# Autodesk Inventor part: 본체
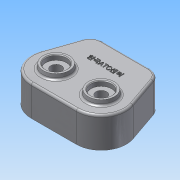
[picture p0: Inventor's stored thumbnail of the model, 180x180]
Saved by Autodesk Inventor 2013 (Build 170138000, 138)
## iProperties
Created: 2014-12
Part Number: 본체
Material: 알루미늄 6061
Document SubType Name: Modeling
Designer: Administrator
Density: 2.71 g/cm^3
Mass: 613.436 g
Surface Area: 665.181 cm^2
Volume: 226.36 cm^3
Author: Administrator
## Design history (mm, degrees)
sketch "스케치1"
  geometry: L1 (47, 36)-(-47, 36); L2 (32.527, -68.527)-(-32.527, -68.527); L3 (47, 36)-(66.565, -20.803); L4 (-47, 36)-(-66.565, -20.803); A1 r 36 centre (32.527, -32.527) between (32.527, -68.527) and (66.565, -20.803); A2 r 36 centre (-32.527, -32.527) between (-66.565, -20.803) and (-32.527, -68.527); 3 further points
  constraints: 8 end point, 4 point on circle, 3 tangent, 2 centre point, 2 midpoint, 2 vertical alignment, 1 horizontal, 1 horizontal alignment
  dimensions: "d18" = 94 distance of L1.start L1.end; "d19" = 72 diameter of A1; "d20" = 72 diameter of A2; "d21" = 36 distance from line of point (0, 0) L1; "d22" = 46 distance of A1.centre point (0, 0); "d23" = 90 deg dimension on point (0, 0) A2.centre A1.centre; "d24" = 46 distance of A2.centre point (0, 0)
extrude "돌출1" new body sketch "스케치1" distance "d25" = 44; taper "d26" = 0 deg
sketch "스케치2"
  geometry: L1 (-43.434, 31)-(43.434, 31); L2 (43.434, 31)-(61.837, -22.432); L3 (-43.434, 31)-(-61.837, -22.432); L4 (-66.565, -20.803)-(-47, 36) reference; L5 (47, 36)-(66.565, -20.803) reference; L6 (-32.527, -63.527)-(32.527, -63.527); L7 (-47, 36)-(47, 36) reference; A1 r 36 centre (-32.527, -32.527) between (-66.565, -20.803) and (-32.527, -68.527) reference; A2 r 36 centre (32.527, -32.527) between (32.527, -68.527) and (66.565, -20.803) reference; A3 r 31 centre (-32.527, -32.527) between (-61.837, -22.432) and (-32.527, -63.527); A4 r 31 centre (32.527, -32.527) between (32.527, -63.527) and (61.837, -22.432); 1 further point
  constraints: 8 end point, 4 point on circle, 3 parallel, 3 tangent, 2 centre point, 2 coincident, 1 horizontal
  dimensions: "d29" = 5 distance between parallel lines of L4 L3; "d30" = 5 distance between parallel lines of L7 L1; "d31" = 5 distance between parallel lines of L2 L5
extrude "돌출2" cut sketch "스케치2" distance "d32" = 34; taper "d33" = 0 deg
sketch "스케치3"
  geometry: L1 (47, 36)-(-47, 36) reference; L2 (-47, 36)-(-66.565, -20.803) reference; L3 (-32.527, -68.527)-(32.527, -68.527) reference; L4 (66.565, -20.803)-(47, 36) reference; C1 r 20 at (-32.527, -32.527); C2 r 20 at (32.527, -32.527); A1 r 36 centre (-32.527, -32.527) between (-66.565, -20.803) and (-32.527, -68.527) reference; A2 r 36 centre (32.527, -32.527) between (32.527, -68.527) and (66.565, -20.803) reference; A3 r 36 centre (-32.527, -32.527) between (-66.565, -20.803) and (-32.527, -68.527) reference; A4 r 36 centre (32.527, -32.527) between (32.527, -68.527) and (66.565, -20.803) reference; 1 further point
  constraints: 2 centre point, 2 coincident
  dimensions: "d34" = 40 diameter of C1; "d35" = 40 diameter of C2
extrude "돌출3" join sketch "스케치3" distance "d36" = 7; taper "d37" = -10 deg
sketch "스케치4"
  geometry: A1 r 36 centre (-32.527, -32.527) between (-66.565, -20.803) and (-32.527, -68.527) reference; A2 r 36 centre (32.527, -32.527) between (32.527, -68.527) and (66.565, -20.803) reference; A3 r 24 centre (-32.527, -32.527) between (-21.111, -11.416) and (-11.416, -21.111); A4 r 24 centre (32.527, -32.527) between (11.416, -21.111) and (21.111, -11.416); A5 r 24 centre (0, 0) between (-11.416, -21.111) and (11.416, -21.111); A6 r 24 centre (0, 0) between (21.111, -11.416) and (-21.111, -11.416); 1 further point
  constraints: 8 point on circle, 4 centre point, 3 coincident
  dimensions: "d39" = 48 diameter of A3; "d40" = 48 diameter of A4; "d41" = 24 radius of A6; "d42" = 24 radius of A5
extrude "돌출4" join sketch "스케치4" distance "d43" = 11; taper "d44" = 0 deg
hole "구멍1" diameter "d47" = 20; stored, may be unused: countersink angle "d51" = 90 deg, drill point angle "d53" = 0 deg; dims "d45" = 10, "d46" = 10, "d48" = 6, "d49" = 40, "d50" = 12, "d52" = 15
hole "구멍2" diameter "d56" = 15.5; stored, may be unused: countersink angle "d60" = 90 deg, drill point angle "d62" = 0 deg; dims "d54" = 10, "d55" = 10, "d57" = 6, "d58" = 35, "d59" = 11, "d61" = 21
hole "구멍3" diameter "d65" = 15.5; stored, may be unused: countersink angle "d69" = 90 deg, drill point angle "d71" = 0 deg; dims "d63" = 10, "d64" = 10, "d66" = 6, "d67" = 35, "d68" = 11, "d70" = 21
sketch "스케치5"
  geometry: C1 r 18.766 at (0, 0) reference; C2 r 18.766 at (65.054, 0) reference; C3 r 15 at (0, 0); C4 r 15 at (65.054, 0); 1 further point
  constraints: 2 centre point, 2 coincident
  dimensions: "d72" = 30 diameter of C3; "d73" = 30 diameter of C4
extrude "돌출5" cut sketch "스케치5" distance "d74" = 7; taper "d75" = 0 deg
sketch "스케치6"
  geometry: L1 (-47, 36)-(47, 36) reference; L2 (32.527, -63.527)-(-32.527, -63.527) reference; L3 (-61.837, -22.432)-(-43.434, 31) reference; L4 (43.434, 31)-(61.837, -22.432) reference; A1 r 8 centre (-51.7, 7) between (-54.305, -0.564) and (-49.095, 14.564); A2 r 8 centre (51.7, 7) between (49.095, 14.564) and (54.305, -0.564); A3 r 8 centre (0, -63.527) between (8, -63.527) and (-8, -63.527); 2 further points
  constraints: 8 point on line, 6 point on circle, 3 centre point, 1 coincident, 1 horizontal alignment, 1 midpoint, 1 vertical alignment
  dimensions: "d76" = 16 diameter of A1; "d77" = 16 diameter of A2; "d78" = 29 distance from line of A2.centre L1; "d79" = 16 diameter of A3
extrude "돌출6" join sketch "스케치6" stored distance "d80" = 7; taper "d81" = 0 deg
fillet "모깎기1" dims "d82" = 18, "d83" = 13
sketch "스케치7"
  geometry: A1 r 8 centre (-51.7, 7) between (-54.305, -0.564) and (-49.095, 14.564) reference; A2 r 8 centre (51.7, 7) between (49.095, 14.564) and (54.305, -0.564) reference; A3 r 8 centre (0, -63.527) between (8, -63.527) and (-8, -63.527) reference; 4 further points
  constraints: 3 coincident
hole "구멍4" sketch "스케치7" at (-51.7, 7), (51.7, 7), (0, -63.527) diameter "d84" = 4.134; stored, may be unused: countersink angle "d88" = 90 deg, drill point angle "d90" = 118 deg; dims "d85" = 20, "d86" = 35, "d87" = 11, "d89" = 23
fillet "모깎기2" dims "d91" = 0.3, "d92" = 0.1, "d93" = 3
chamfer "모따기1" distance "d94" = 1; stored, may be unused: second distance "d95" = 2, angle "d96" = 45 deg
sketch "스케치8"
  geometry: L1 (34.162, 36)-(-34.162, 36) reference; 2 further points
  constraints: 1 vertical alignment, 1 other
  dimensions: "d97" = 30 distance from line of point (0, 6) L1
feature "엠보싱1" sketch "스케치8" dims "d98" = 1, "d99" = 0
node "솔리드1"
node "투영된 루프1"
other parameters: "d38" = 48
